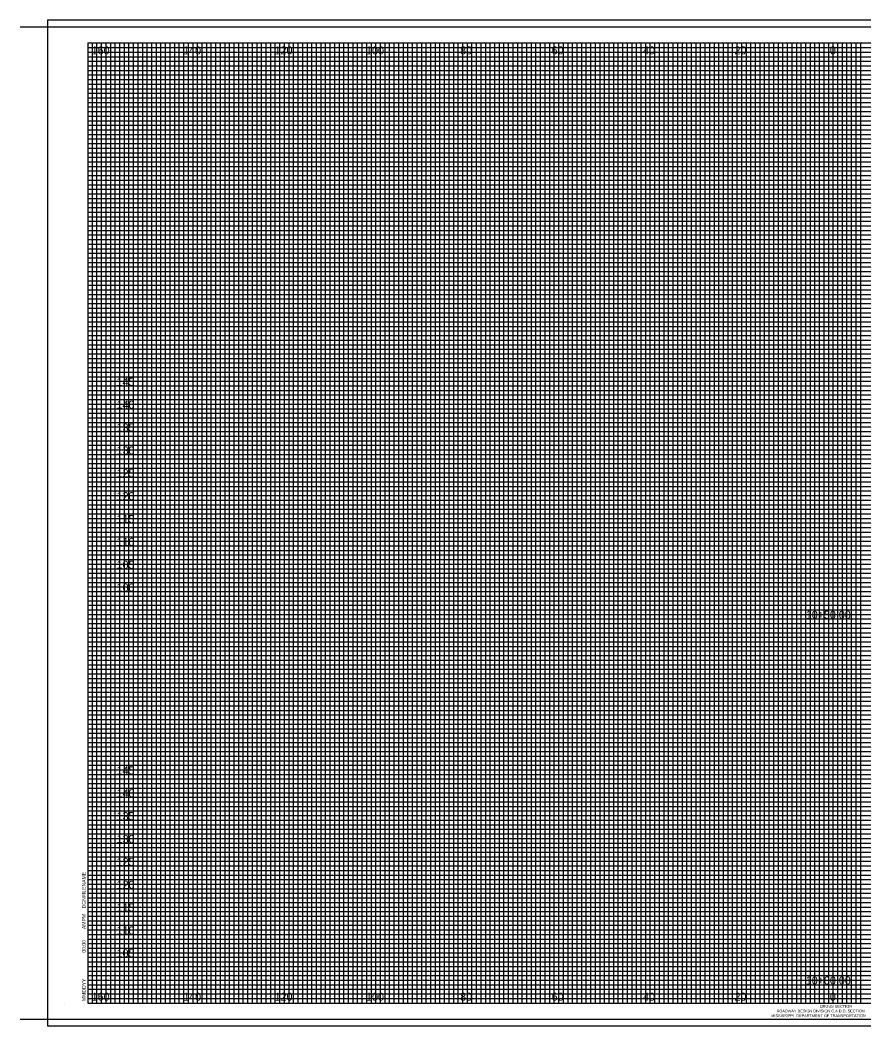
# Model space of a CAD drawing. Extents: x 21465 to 21817, y 6470 to 8070.
# Drawn here: x 21465 to 21649.5, y 6469.8 to 6689.8 of the extents above; entities that cross this region are included whole.
import ezdxf

# ---------------------------------------------------------------- set-up
doc = ezdxf.new("R2010")
doc.units = 0
for name, color, linetype in [('SHEET_BORDER', 7, 'Continuous'), ('SHEET_BORDER_TX', 7, 'Continuous'), ('SHEET_DATE_DGN_TX', 7, 'Continuous'), ('SHEET_PLOTTING_SHAPE', 7, 'Continuous'), ('XS_SHEET_LABELS_ELEVATION', 7, 'Continuous'), ('XS_SHEET_LABELS_OFFSET', 7, 'Continuous'), ('XS_SHEET_LABELS_STATION', 7, 'Continuous'), ('XS_SHEET_MAJOR_GRIDS', 7, 'Continuous'), ('XS_SHEET_MEDIUM_GRIDS', 7, 'Continuous'), ('XS_SHEET_MINOR_GRIDS', 7, 'Continuous')]:
    doc.layers.add(name, color=color, linetype=linetype)

msp = doc.modelspace()

# ---------------------------------------------------------------- linework, layer by layer
at = {"layer": 'SHEET_BORDER'}
for p, q in [((21465.04, 6688.34), (21817.04, 6688.34)), ((21479.84, 6684.84), (21814.84, 6684.84)), ((21479.84, 6684.84), (21479.84, 6474.84)), ((21623.84, 6474.84), (21623.84, 6684.84)), ((21474.84, 6474.84), (21474.84, 6474.84)), ((21479.84, 6474.84), (21814.84, 6474.84)), ((21465.04, 6471.34), (21817.04, 6471.34))]:
    msp.add_line(p, q, dxfattribs=at)
at = {"layer": 'SHEET_PLOTTING_SHAPE'}
msp.add_lwpolyline([(21471.04, 6469.84), (21817.04, 6469.84), (21817.04, 6689.84), (21471.04, 6689.84)], close=True, dxfattribs=at)
at = {"layer": 'XS_SHEET_MAJOR_GRIDS'}
for p, q in [((21484.84, 6474.84), (21484.84, 6684.84)), ((21494.84, 6474.84), (21494.84, 6684.84)), ((21504.84, 6474.84), (21504.84, 6684.84)), ((21514.84, 6474.84), (21514.84, 6684.84)), ((21524.84, 6474.84), (21524.84, 6684.84)), ((21534.84, 6474.84), (21534.84, 6684.84)), ((21544.84, 6474.84), (21544.84, 6684.84)), ((21554.84, 6474.84), (21554.84, 6684.84)), ((21564.84, 6474.84), (21564.84, 6684.84)), ((21574.84, 6474.84), (21574.84, 6684.84)), ((21584.84, 6474.84), (21584.84, 6684.84)), ((21594.84, 6474.84), (21594.84, 6684.84)), ((21604.84, 6474.84), (21604.84, 6684.84)), ((21614.84, 6474.84), (21614.84, 6684.84)), ((21624.84, 6474.84), (21624.84, 6684.84)), ((21634.84, 6474.84), (21634.84, 6684.84)), ((21644.84, 6474.84), (21644.84, 6684.84)), ((21479.84, 6674.84), (21814.84, 6674.84)), ((21479.84, 6664.84), (21814.84, 6664.84)), ((21479.84, 6654.84), (21814.84, 6654.84)), ((21479.84, 6644.84), (21814.84, 6644.84)), ((21479.84, 6634.84), (21814.84, 6634.84)), ((21479.84, 6624.84), (21814.84, 6624.84)), ((21479.84, 6614.84), (21814.84, 6614.84)), ((21479.84, 6604.84), (21814.84, 6604.84)), ((21479.84, 6594.84), (21814.84, 6594.84)), ((21479.84, 6584.84), (21814.84, 6584.84)), ((21479.84, 6574.84), (21814.84, 6574.84)), ((21479.84, 6564.84), (21814.84, 6564.84)), ((21479.84, 6554.84), (21814.84, 6554.84)), ((21479.84, 6544.84), (21814.84, 6544.84)), ((21479.84, 6534.84), (21814.84, 6534.84)), ((21479.84, 6524.84), (21814.84, 6524.84)), ((21479.84, 6514.84), (21814.84, 6514.84)), ((21479.84, 6504.84), (21814.84, 6504.84)), ((21479.84, 6494.84), (21814.84, 6494.84)), ((21479.84, 6484.84), (21814.84, 6484.84))]:
    msp.add_line(p, q, dxfattribs=at)
at = {"layer": 'XS_SHEET_MEDIUM_GRIDS'}
for p, q in [((21489.84, 6474.84), (21489.84, 6684.84)), ((21499.84, 6474.84), (21499.84, 6684.84)), ((21509.84, 6474.84), (21509.84, 6684.84)), ((21519.84, 6474.84), (21519.84, 6684.84)), ((21529.84, 6474.84), (21529.84, 6684.84)), ((21539.84, 6474.84), (21539.84, 6684.84)), ((21549.84, 6474.84), (21549.84, 6684.84)), ((21559.84, 6474.84), (21559.84, 6684.84)), ((21569.84, 6474.84), (21569.84, 6684.84)), ((21579.84, 6474.84), (21579.84, 6684.84)), ((21589.84, 6474.84), (21589.84, 6684.84)), ((21599.84, 6474.84), (21599.84, 6684.84)), ((21609.84, 6474.84), (21609.84, 6684.84)), ((21619.84, 6474.84), (21619.84, 6684.84)), ((21629.84, 6474.84), (21629.84, 6684.84)), ((21639.84, 6474.84), (21639.84, 6684.84)), ((21479.84, 6679.84), (21787.84, 6679.84)), ((21479.84, 6669.84), (21814.84, 6669.84)), ((21479.84, 6659.84), (21814.84, 6659.84)), ((21479.84, 6649.84), (21814.84, 6649.84)), ((21479.84, 6639.84), (21814.84, 6639.84)), ((21479.84, 6629.84), (21814.84, 6629.84)), ((21479.84, 6619.84), (21814.84, 6619.84)), ((21479.84, 6609.84), (21814.84, 6609.84)), ((21479.84, 6599.84), (21814.84, 6599.84)), ((21479.84, 6589.84), (21814.84, 6589.84)), ((21479.84, 6579.84), (21814.84, 6579.84)), ((21479.84, 6569.84), (21814.84, 6569.84)), ((21479.84, 6559.84), (21814.84, 6559.84)), ((21479.84, 6549.84), (21814.84, 6549.84)), ((21479.84, 6539.84), (21814.84, 6539.84)), ((21479.84, 6529.84), (21814.84, 6529.84)), ((21479.84, 6519.84), (21814.84, 6519.84)), ((21479.84, 6509.84), (21814.84, 6509.84)), ((21479.84, 6499.84), (21814.84, 6499.84)), ((21479.84, 6489.84), (21814.84, 6489.84)), ((21479.84, 6479.84), (21804.84, 6479.84))]:
    msp.add_line(p, q, dxfattribs=at)
at = {"layer": 'XS_SHEET_MINOR_GRIDS'}
for p, q in [((21479.84, 6683.84), (21787.84, 6683.84)), ((21480.84, 6474.84), (21480.84, 6684.84)), ((21481.84, 6474.84), (21481.84, 6684.84)), ((21482.84, 6474.84), (21482.84, 6684.84)), ((21483.84, 6474.84), (21483.84, 6684.84)), ((21485.84, 6474.84), (21485.84, 6684.84)), ((21486.84, 6474.84), (21486.84, 6684.84)), ((21487.84, 6474.84), (21487.84, 6684.84)), ((21488.84, 6474.84), (21488.84, 6684.84)), ((21490.84, 6474.84), (21490.84, 6684.84)), ((21491.84, 6474.84), (21491.84, 6684.84)), ((21492.84, 6474.84), (21492.84, 6684.84)), ((21493.84, 6474.84), (21493.84, 6684.84)), ((21495.84, 6474.84), (21495.84, 6684.84)), ((21496.84, 6474.84), (21496.84, 6684.84)), ((21497.84, 6474.84), (21497.84, 6684.84)), ((21498.84, 6474.84), (21498.84, 6684.84)), ((21500.84, 6474.84), (21500.84, 6684.84)), ((21501.84, 6474.84), (21501.84, 6684.84)), ((21502.84, 6474.84), (21502.84, 6684.84)), ((21503.84, 6474.84), (21503.84, 6684.84)), ((21505.84, 6474.84), (21505.84, 6684.84)), ((21506.84, 6474.84), (21506.84, 6684.84)), ((21507.84, 6474.84), (21507.84, 6684.84)), ((21508.84, 6474.84), (21508.84, 6684.84)), ((21510.84, 6474.84), (21510.84, 6684.84)), ((21511.84, 6474.84), (21511.84, 6684.84)), ((21512.84, 6474.84), (21512.84, 6684.84)), ((21513.84, 6474.84), (21513.84, 6684.84)), ((21515.84, 6474.84), (21515.84, 6684.84)), ((21516.84, 6474.84), (21516.84, 6684.84)), ((21517.84, 6474.84), (21517.84, 6684.84)), ((21518.84, 6474.84), (21518.84, 6684.84)), ((21520.84, 6474.84), (21520.84, 6684.84)), ((21521.84, 6474.84), (21521.84, 6684.84)), ((21522.84, 6474.84), (21522.84, 6684.84)), ((21523.84, 6474.84), (21523.84, 6684.84)), ((21525.84, 6474.84), (21525.84, 6684.84)), ((21526.84, 6474.84), (21526.84, 6684.84)), ((21527.84, 6474.84), (21527.84, 6684.84)), ((21528.84, 6474.84), (21528.84, 6684.84)), ((21530.84, 6474.84), (21530.84, 6684.84)), ((21531.84, 6474.84), (21531.84, 6684.84)), ((21532.84, 6474.84), (21532.84, 6684.84)), ((21533.84, 6474.84), (21533.84, 6684.84)), ((21535.84, 6474.84), (21535.84, 6684.84)), ((21536.84, 6474.84), (21536.84, 6684.84)), ((21537.84, 6474.84), (21537.84, 6684.84)), ((21538.84, 6474.84), (21538.84, 6684.84)), ((21540.84, 6474.84), (21540.84, 6684.84)), ((21541.84, 6474.84), (21541.84, 6684.84)), ((21542.84, 6474.84), (21542.84, 6684.84)), ((21543.84, 6474.84), (21543.84, 6684.84)), ((21545.84, 6474.84), (21545.84, 6684.84)), ((21546.84, 6474.84), (21546.84, 6684.84)), ((21547.84, 6474.84), (21547.84, 6684.84)), ((21548.84, 6474.84), (21548.84, 6684.84)), ((21550.84, 6474.84), (21550.84, 6684.84)), ((21551.84, 6474.84), (21551.84, 6684.84)), ((21552.84, 6474.84), (21552.84, 6684.84)), ((21553.84, 6474.84), (21553.84, 6684.84)), ((21555.84, 6474.84), (21555.84, 6684.84)), ((21556.84, 6474.84), (21556.84, 6684.84)), ((21557.84, 6474.84), (21557.84, 6684.84)), ((21558.84, 6474.84), (21558.84, 6684.84)), ((21560.84, 6474.84), (21560.84, 6684.84)), ((21561.84, 6474.84), (21561.84, 6684.84)), ((21562.84, 6474.84), (21562.84, 6684.84)), ((21563.84, 6474.84), (21563.84, 6684.84)), ((21565.84, 6474.84), (21565.84, 6684.84)), ((21566.84, 6474.84), (21566.84, 6684.84)), ((21567.84, 6474.84), (21567.84, 6684.84)), ((21568.84, 6474.84), (21568.84, 6684.84)), ((21570.84, 6474.84), (21570.84, 6684.84)), ((21571.84, 6474.84), (21571.84, 6684.84)), ((21572.84, 6474.84), (21572.84, 6684.84)), ((21573.84, 6474.84), (21573.84, 6684.84)), ((21575.84, 6474.84), (21575.84, 6684.84)), ((21576.84, 6474.84), (21576.84, 6684.84)), ((21577.84, 6474.84), (21577.84, 6684.84)), ((21578.84, 6474.84), (21578.84, 6684.84)), ((21580.84, 6474.84), (21580.84, 6684.84)), ((21581.84, 6474.84), (21581.84, 6684.84)), ((21582.84, 6474.84), (21582.84, 6684.84)), ((21583.84, 6474.84), (21583.84, 6684.84)), ((21585.84, 6474.84), (21585.84, 6684.84)), ((21586.84, 6474.84), (21586.84, 6684.84)), ((21587.84, 6474.84), (21587.84, 6684.84)), ((21588.84, 6474.84), (21588.84, 6684.84)), ((21590.84, 6474.84), (21590.84, 6684.84)), ((21591.84, 6474.84), (21591.84, 6684.84)), ((21592.84, 6474.84), (21592.84, 6684.84)), ((21593.84, 6474.84), (21593.84, 6684.84)), ((21595.84, 6474.84), (21595.84, 6684.84)), ((21596.84, 6474.84), (21596.84, 6684.84)), ((21597.84, 6474.84), (21597.84, 6684.84)), ((21598.84, 6474.84), (21598.84, 6684.84)), ((21600.84, 6474.84), (21600.84, 6684.84)), ((21601.84, 6474.84), (21601.84, 6684.84)), ((21602.84, 6474.84), (21602.84, 6684.84)), ((21603.84, 6474.84), (21603.84, 6684.84)), ((21605.84, 6474.84), (21605.84, 6684.84)), ((21606.84, 6474.84), (21606.84, 6684.84)), ((21607.84, 6474.84), (21607.84, 6684.84)), ((21608.84, 6474.84), (21608.84, 6684.84)), ((21610.84, 6474.84), (21610.84, 6684.84)), ((21611.84, 6474.84), (21611.84, 6684.84)), ((21612.84, 6474.84), (21612.84, 6684.84)), ((21613.84, 6474.84), (21613.84, 6684.84)), ((21615.84, 6474.84), (21615.84, 6684.84)), ((21616.84, 6474.84), (21616.84, 6684.84)), ((21617.84, 6474.84), (21617.84, 6684.84)), ((21618.84, 6474.84), (21618.84, 6684.84)), ((21620.84, 6474.84), (21620.84, 6684.84)), ((21621.84, 6474.84), (21621.84, 6684.84)), ((21622.84, 6474.84), (21622.84, 6684.84)), ((21625.84, 6474.84), (21625.84, 6684.84)), ((21626.84, 6474.84), (21626.84, 6684.84)), ((21627.84, 6474.84), (21627.84, 6684.84)), ((21628.84, 6474.84), (21628.84, 6684.84)), ((21630.84, 6474.84), (21630.84, 6684.84)), ((21631.84, 6474.84), (21631.84, 6684.84)), ((21632.84, 6474.84), (21632.84, 6684.84)), ((21633.84, 6474.84), (21633.84, 6684.84)), ((21635.84, 6474.84), (21635.84, 6684.84)), ((21636.84, 6474.84), (21636.84, 6684.84)), ((21637.84, 6474.84), (21637.84, 6684.84)), ((21638.84, 6474.84), (21638.84, 6684.84)), ((21640.84, 6474.84), (21640.84, 6684.84)), ((21641.84, 6474.84), (21641.84, 6684.84)), ((21642.84, 6474.84), (21642.84, 6684.84)), ((21643.84, 6474.84), (21643.84, 6684.84)), ((21645.84, 6474.84), (21645.84, 6684.84)), ((21646.84, 6474.84), (21646.84, 6684.84)), ((21647.84, 6474.84), (21647.84, 6684.84)), ((21648.84, 6474.84), (21648.84, 6684.84)), ((21479.84, 6682.84), (21787.84, 6682.84)), ((21479.84, 6681.84), (21787.84, 6681.84)), ((21479.84, 6680.84), (21787.84, 6680.84)), ((21479.84, 6678.84), (21787.84, 6678.84)), ((21479.84, 6677.84), (21787.84, 6677.84)), ((21479.84, 6676.84), (21787.84, 6676.84)), ((21479.84, 6675.84), (21814.84, 6675.84)), ((21479.84, 6673.84), (21814.84, 6673.84)), ((21479.84, 6672.84), (21814.84, 6672.84)), ((21479.84, 6671.84), (21814.84, 6671.84)), ((21479.84, 6670.84), (21814.84, 6670.84)), ((21479.84, 6668.84), (21814.84, 6668.84)), ((21479.84, 6667.84), (21814.84, 6667.84)), ((21479.84, 6666.84), (21814.84, 6666.84)), ((21479.84, 6665.84), (21814.84, 6665.84)), ((21479.84, 6663.84), (21814.84, 6663.84)), ((21479.84, 6662.84), (21814.84, 6662.84)), ((21479.84, 6661.84), (21814.84, 6661.84)), ((21479.84, 6660.84), (21814.84, 6660.84)), ((21479.84, 6658.84), (21814.84, 6658.84)), ((21479.84, 6657.84), (21814.84, 6657.84)), ((21479.84, 6656.84), (21814.84, 6656.84)), ((21479.84, 6655.84), (21814.84, 6655.84)), ((21479.84, 6653.84), (21814.84, 6653.84)), ((21479.84, 6652.84), (21814.84, 6652.84)), ((21479.84, 6651.84), (21814.84, 6651.84)), ((21479.84, 6650.84), (21814.84, 6650.84)), ((21479.84, 6648.84), (21814.84, 6648.84)), ((21479.84, 6647.84), (21814.84, 6647.84)), ((21479.84, 6646.84), (21814.84, 6646.84)), ((21479.84, 6645.84), (21814.84, 6645.84)), ((21479.84, 6643.84), (21814.84, 6643.84)), ((21479.84, 6642.84), (21814.84, 6642.84)), ((21479.84, 6641.84), (21814.84, 6641.84)), ((21479.84, 6640.84), (21814.84, 6640.84)), ((21479.84, 6638.84), (21814.84, 6638.84)), ((21479.84, 6637.84), (21814.84, 6637.84)), ((21479.84, 6636.84), (21814.84, 6636.84)), ((21479.84, 6635.84), (21814.84, 6635.84)), ((21479.84, 6633.84), (21814.84, 6633.84)), ((21479.84, 6632.84), (21814.84, 6632.84)), ((21479.84, 6631.84), (21814.84, 6631.84)), ((21479.84, 6630.84), (21814.84, 6630.84)), ((21479.84, 6628.84), (21814.84, 6628.84)), ((21479.84, 6627.84), (21814.84, 6627.84)), ((21479.84, 6626.84), (21814.84, 6626.84)), ((21479.84, 6625.84), (21814.84, 6625.84)), ((21479.84, 6623.84), (21814.84, 6623.84)), ((21479.84, 6622.84), (21814.84, 6622.84)), ((21479.84, 6621.84), (21814.84, 6621.84)), ((21479.84, 6620.84), (21814.84, 6620.84)), ((21479.84, 6618.84), (21814.84, 6618.84)), ((21479.84, 6617.84), (21814.84, 6617.84)), ((21479.84, 6616.84), (21814.84, 6616.84)), ((21479.84, 6615.84), (21814.84, 6615.84)), ((21479.84, 6613.84), (21814.84, 6613.84)), ((21479.84, 6612.84), (21814.84, 6612.84)), ((21479.84, 6611.84), (21814.84, 6611.84)), ((21479.84, 6610.84), (21814.84, 6610.84)), ((21479.84, 6608.84), (21814.84, 6608.84)), ((21479.84, 6607.84), (21814.84, 6607.84)), ((21479.84, 6606.84), (21814.84, 6606.84)), ((21479.84, 6605.84), (21814.84, 6605.84)), ((21479.84, 6603.84), (21814.84, 6603.84)), ((21479.84, 6602.84), (21814.84, 6602.84)), ((21479.84, 6601.84), (21814.84, 6601.84)), ((21479.84, 6600.84), (21814.84, 6600.84)), ((21479.84, 6598.84), (21814.84, 6598.84)), ((21479.84, 6597.84), (21814.84, 6597.84)), ((21479.84, 6596.84), (21814.84, 6596.84)), ((21479.84, 6595.84), (21814.84, 6595.84)), ((21479.84, 6593.84), (21814.84, 6593.84)), ((21479.84, 6592.84), (21814.84, 6592.84)), ((21479.84, 6591.84), (21814.84, 6591.84)), ((21479.84, 6590.84), (21814.84, 6590.84)), ((21479.84, 6588.84), (21814.84, 6588.84)), ((21479.84, 6587.84), (21814.84, 6587.84)), ((21479.84, 6586.84), (21814.84, 6586.84)), ((21479.84, 6585.84), (21814.84, 6585.84)), ((21479.84, 6583.84), (21814.84, 6583.84)), ((21479.84, 6582.84), (21814.84, 6582.84)), ((21479.84, 6581.84), (21814.84, 6581.84)), ((21479.84, 6580.84), (21814.84, 6580.84)), ((21479.84, 6578.84), (21814.84, 6578.84)), ((21479.84, 6577.84), (21814.84, 6577.84)), ((21479.84, 6576.84), (21814.84, 6576.84)), ((21479.84, 6575.84), (21814.84, 6575.84)), ((21479.84, 6573.84), (21814.84, 6573.84)), ((21479.84, 6572.84), (21814.84, 6572.84)), ((21479.84, 6571.84), (21814.84, 6571.84)), ((21479.84, 6570.84), (21814.84, 6570.84)), ((21479.84, 6568.84), (21814.84, 6568.84)), ((21479.84, 6567.84), (21814.84, 6567.84)), ((21479.84, 6566.84), (21814.84, 6566.84)), ((21479.84, 6565.84), (21814.84, 6565.84)), ((21479.84, 6563.84), (21814.84, 6563.84)), ((21479.84, 6562.84), (21814.84, 6562.84)), ((21479.84, 6561.84), (21814.84, 6561.84)), ((21479.84, 6560.84), (21814.84, 6560.84)), ((21479.84, 6558.84), (21814.84, 6558.84)), ((21479.84, 6557.84), (21814.84, 6557.84)), ((21479.84, 6556.84), (21814.84, 6556.84)), ((21479.84, 6555.84), (21814.84, 6555.84)), ((21479.84, 6553.84), (21814.84, 6553.84)), ((21479.84, 6552.84), (21814.84, 6552.84)), ((21479.84, 6551.84), (21814.84, 6551.84)), ((21479.84, 6550.84), (21814.84, 6550.84)), ((21479.84, 6548.84), (21814.84, 6548.84)), ((21479.84, 6547.84), (21814.84, 6547.84)), ((21479.84, 6546.84), (21814.84, 6546.84)), ((21479.84, 6545.84), (21814.84, 6545.84)), ((21479.84, 6543.84), (21814.84, 6543.84)), ((21479.84, 6542.84), (21814.84, 6542.84)), ((21479.84, 6541.84), (21814.84, 6541.84)), ((21479.84, 6540.84), (21814.84, 6540.84)), ((21479.84, 6538.84), (21814.84, 6538.84)), ((21479.84, 6537.84), (21814.84, 6537.84)), ((21479.84, 6536.84), (21814.84, 6536.84)), ((21479.84, 6535.84), (21814.84, 6535.84)), ((21479.84, 6533.84), (21814.84, 6533.84)), ((21479.84, 6532.84), (21814.84, 6532.84)), ((21479.84, 6531.84), (21814.84, 6531.84)), ((21479.84, 6530.84), (21814.84, 6530.84)), ((21479.84, 6528.84), (21814.84, 6528.84)), ((21479.84, 6527.84), (21814.84, 6527.84)), ((21479.84, 6526.84), (21814.84, 6526.84)), ((21479.84, 6525.84), (21814.84, 6525.84)), ((21479.84, 6523.84), (21814.84, 6523.84)), ((21479.84, 6522.84), (21814.84, 6522.84)), ((21479.84, 6521.84), (21814.84, 6521.84)), ((21479.84, 6520.84), (21814.84, 6520.84)), ((21479.84, 6518.84), (21814.84, 6518.84)), ((21479.84, 6517.84), (21814.84, 6517.84)), ((21479.84, 6516.84), (21814.84, 6516.84)), ((21479.84, 6515.84), (21814.84, 6515.84)), ((21479.84, 6513.84), (21814.84, 6513.84)), ((21479.84, 6512.84), (21814.84, 6512.84)), ((21479.84, 6511.84), (21814.84, 6511.84)), ((21479.84, 6510.84), (21814.84, 6510.84)), ((21479.84, 6508.84), (21814.84, 6508.84)), ((21479.84, 6507.84), (21814.84, 6507.84)), ((21479.84, 6506.84), (21814.84, 6506.84)), ((21479.84, 6505.84), (21814.84, 6505.84)), ((21479.84, 6503.84), (21814.84, 6503.84)), ((21479.84, 6502.84), (21814.84, 6502.84)), ((21479.84, 6501.84), (21814.84, 6501.84)), ((21479.84, 6500.84), (21814.84, 6500.84)), ((21479.84, 6498.84), (21814.84, 6498.84)), ((21479.84, 6497.84), (21814.84, 6497.84)), ((21479.84, 6496.84), (21814.84, 6496.84)), ((21479.84, 6495.84), (21814.84, 6495.84)), ((21479.84, 6495.84), (21814.84, 6495.84)), ((21479.84, 6495.84), (21814.84, 6495.84)), ((21479.84, 6493.84), (21814.84, 6493.84)), ((21479.84, 6492.84), (21814.84, 6492.84)), ((21479.84, 6491.84), (21814.84, 6491.84)), ((21479.84, 6490.84), (21814.84, 6490.84)), ((21479.84, 6488.84), (21814.84, 6488.84)), ((21479.84, 6487.84), (21814.84, 6487.84)), ((21479.84, 6486.84), (21814.84, 6486.84)), ((21479.84, 6485.84), (21814.84, 6485.84)), ((21479.84, 6483.84), (21804.84, 6483.84)), ((21479.84, 6482.84), (21804.84, 6482.84)), ((21479.84, 6481.84), (21804.84, 6481.84)), ((21479.84, 6480.84), (21804.84, 6480.84)), ((21479.84, 6480.84), (21804.84, 6480.84)), ((21479.84, 6480.84), (21804.84, 6480.84)), ((21479.84, 6478.84), (21804.84, 6478.84)), ((21479.84, 6477.84), (21804.84, 6477.84)), ((21479.84, 6476.84), (21804.84, 6476.84)), ((21479.84, 6475.84), (21804.84, 6475.84))]:
    msp.add_line(p, q, dxfattribs=at)

# ---------------------------------------------------------------- texts
at = {"layer": 'SHEET_BORDER_TX'}
for s, height, p in [('ROADWAY DESIGN DIVISION C.A.D.D. SECTION', 0.61, (21630.44, 6472.78)), ('CROSS SECTION', 0.62, (21639.87, 6473.81)), ('MISSISSIPPI  DEPARTMENT OF TRANSPORTATION', 0.61, (21629.27, 6471.75))]:
    msp.add_text(s, height=height, dxfattribs=at).set_placement(p)
at = {"layer": 'SHEET_DATE_DGN_TX'}
for s, p in [('DGNFILENAME', (21479.37, 6495.54)), ('AMPM', (21479.37, 6491.02)), ('00:00', (21479.37, 6485.84)), ('MMDDYY', (21479.37, 6475.26))]:
    msp.add_text(s, height=0.8, rotation=90, dxfattribs=at).set_placement(p)
at = {"layer": 'XS_SHEET_LABELS_ELEVATION'}
for s, p in [('  145  ', (21484.84, 6609.84)), ('  140  ', (21484.84, 6604.84)), ('  135  ', (21484.84, 6599.84)), ('  130  ', (21484.84, 6594.84)), ('  125  ', (21484.84, 6589.84)), ('  120  ', (21484.84, 6584.84)), ('  115  ', (21484.84, 6579.84)), ('  110  ', (21484.84, 6574.84)), ('  105  ', (21484.84, 6569.84)), ('  100  ', (21484.84, 6564.84)), ('  145  ', (21484.84, 6524.84)), ('  140  ', (21484.84, 6519.84)), ('  135  ', (21484.84, 6514.84)), ('  130  ', (21484.84, 6509.84)), ('  125  ', (21484.84, 6504.84)), ('  120  ', (21484.84, 6499.84)), ('  115  ', (21484.84, 6494.84)), ('  110  ', (21484.84, 6489.84)), ('  105  ', (21484.84, 6484.84))]:
    msp.add_text(s, height=1.75, dxfattribs=at).set_placement(p)
at = {"layer": 'XS_SHEET_LABELS_OFFSET'}
for s, p in [('  160  ', (21479.4, 6682.34)), ('  140  ', (21499.39, 6682.34)), ('  120  ', (21519.39, 6682.34)), ('  100  ', (21539.39, 6682.34)), ('  80  ', (21559.95, 6682.34)), ('  60  ', (21579.97, 6682.34)), ('  40  ', (21599.95, 6682.34)), ('  20  ', (21619.95, 6682.34)), ('  0  ', (21640.81, 6682.34)), ('  0  ', (21640.81, 6682.34)), ('  160  ', (21479.4, 6475.34)), ('  140  ', (21499.39, 6475.34)), ('  120  ', (21519.39, 6475.34)), ('  100  ', (21539.39, 6475.34)), ('  80  ', (21559.95, 6475.34)), ('  60  ', (21579.97, 6475.34)), ('  40  ', (21599.95, 6475.34)), ('  20  ', (21619.95, 6475.34)), ('  0  ', (21640.81, 6475.34)), ('  0  ', (21640.81, 6475.34))]:
    msp.add_text(s, height=1.75, dxfattribs=at).set_placement(p)
at = {"layer": 'XS_SHEET_LABELS_STATION'}
for s, p in [('  10+50.00  ', (21635.54, 6558.89)), ('  10+00.00  ', (21635.54, 6478.89))]:
    msp.add_text(s, height=1.75, dxfattribs=at).set_placement(p)

doc.saveas('drawing.dxf')
